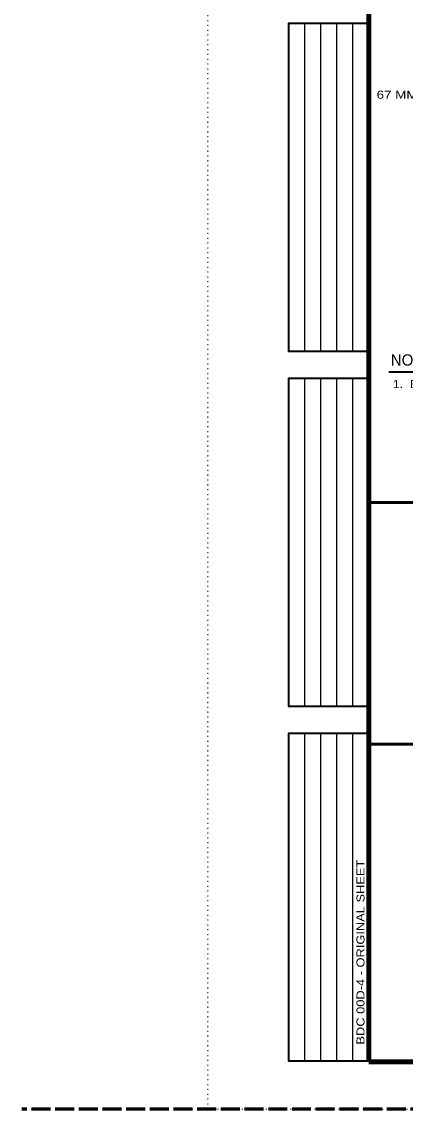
# Model space of a CAD drawing. Extents: x 312583 to 312854, y 144419 to 144597.
# Drawn here: x 312583.5 to 312620, y 144418.6 to 144522 of the extents above; entities that cross this region are included whole.
import ezdxf
from ezdxf.enums import TextEntityAlignment as Align

# ---------------------------------------------------------------- set-up
doc = ezdxf.new("R2010")
doc.units = 0
doc.header["$LTSCALE"] = 0.3
doc.linetypes.add('DOTTED', pattern=[1.5, 0.3, -1.2])
doc.linetypes.add('LONG_DASHED', pattern=[7.5, 6, -1.5])
for name, color, linetype, lineweight in [('1', 7, 'Continuous', 40), ('2', 7, 'Continuous', 13), ('62', 7, 'DOTTED', 13), ('63', 7, 'LONG_DASHED', 60)]:
    doc.layers.add(name, color=color, linetype=linetype, lineweight=lineweight)

msp = doc.modelspace()

# ---------------------------------------------------------------- linework, layer by layer
at = {"layer": '1', "lineweight": 25}
for p, q in [((312610.4087, 144490.6573), (312610.4087, 144521.8756)), ((312611.9315, 144490.6573), (312611.9315, 144521.8756)), ((312613.4543, 144490.6573), (312613.4543, 144521.8756)), ((312614.9772, 144490.6573), (312614.9772, 144521.8756)), ((312610.4087, 144456.901), (312610.4087, 144488.1192)), ((312611.9315, 144456.901), (312611.9315, 144488.1192)), ((312613.4543, 144456.901), (312613.4543, 144488.1192)), ((312614.9772, 144456.901), (312614.9772, 144488.1192)), ((312610.4087, 144423.1446), (312610.4087, 144454.3629)), ((312611.9315, 144423.1446), (312611.9315, 144454.3629)), ((312613.4543, 144423.1446), (312613.4543, 144454.3629)), ((312614.9772, 144423.1446), (312614.9772, 144454.3629))]:
    msp.add_line(p, q, dxfattribs=at)
at = {"layer": '1', "lineweight": 53}
for p, q in [((312770.2547, 144476.2913), (312616.5, 144476.2913)), ((312656.0838, 144453.2989), (312616.5, 144453.2989))]:
    msp.add_line(p, q, dxfattribs=at)
at = {"layer": '1', "lineweight": 158}
msp.add_line((312616.5, 144423.0846), (312849, 144423.0846), dxfattribs=at)
msp.add_lwpolyline([(312616.5, 144423.1446), (312616.5, 144585.0846), (312849, 144585.0846)], dxfattribs=at)
at = {"layer": '1', "lineweight": 35}
for points in [[(312616.5, 144490.6573), (312608.8858, 144490.6573), (312608.8858, 144521.8756), (312616.5, 144521.8756)], [(312616.5, 144456.901), (312608.8858, 144456.901), (312608.8858, 144488.1192), (312616.5, 144488.1192)], [(312616.5, 144423.1446), (312608.8858, 144423.1446), (312608.8858, 144454.3629), (312616.5, 144454.3629)]]:
    msp.add_lwpolyline(points, dxfattribs=at)
at = {"layer": '2', "lineweight": 35}
msp.add_line((312618.4083, 144488.7339), (312623.2, 144488.7339), dxfattribs=at)
at = {"layer": '62'}
msp.add_line((312601.2, 144418.5846), (312601.2, 144596.7846), dxfattribs=at)
msp.add_lwpolyline([(312601.2, 144418.5846), (312853.5, 144418.5846), (312853.5, 144596.7846)], dxfattribs=at)
at = {"layer": '63'}
msp.add_line((312851.75, 144418.5846), (312583.526, 144418.5846), dxfattribs=at)

# ---------------------------------------------------------------- texts
at = {"layer": '1', "width": 1.2}
msp.add_text('BDC 00D-4 - ORIGINAL SHEET', height=0.7614, rotation=90, dxfattribs=at).set_placement((312616.0832, 144424.7374))
at = {"layer": '2'}
for s, width, p in [('67 MM DIA.', 1.25, (312617.2383, 144514.7045)), ('1.  EACH HOLLOW SPIDER FOR 2-WAY ASSEMBLY SHALL CONSIST OF:', 1.15, (312618.7687, 144487.1809))]:
    msp.add_text(s, height=0.76, dxfattribs=dict(at, width=width)).set_placement(p)
msp.add_text('NOTE:', height=1.07, dxfattribs=at).set_placement((312620.7673, 144489.3192), align=Align.CENTER)

doc.saveas('drawing.dxf')
